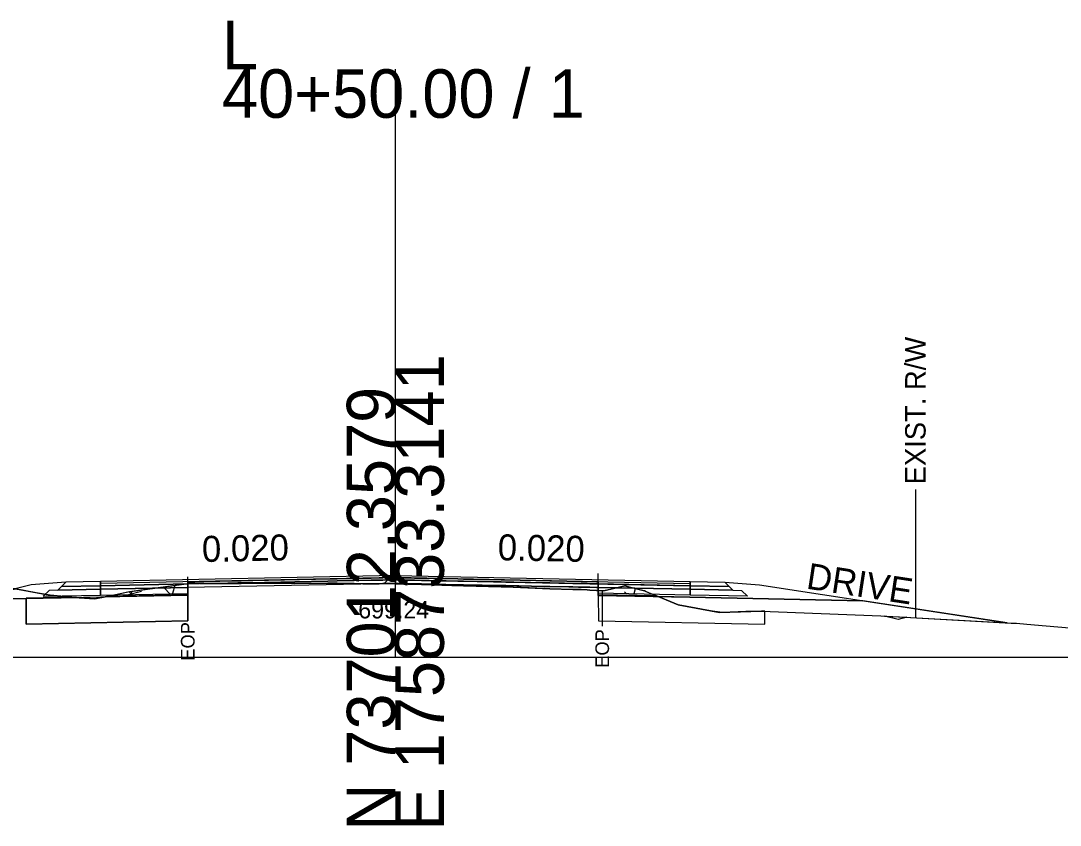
# Model space of a CAD drawing. Extents: x -26 to 4303, y -10 to 9577.
# Drawn here: x 3128.4 to 3188.4, y 490.3 to 536.7 of the extents above; entities that cross this region are included whole.
import ezdxf

# ---------------------------------------------------------------- set-up
doc = ezdxf.new("R2010")
doc.units = 0
for name, color, linetype in [('Exist CMT Pavement', 7, 'Continuous'), ('Old_Level_2', 7, 'Continuous'), ('Pattern 3', 7, 'Continuous'), ('Prop CMT Conc Surface', 7, 'Continuous'), ('Prop CMT Concrete Structures', 7, 'Continuous'), ('Prop CMT Pvmt Course 1', 7, 'Continuous'), ('Prop CMT Pvmt Course 1 CG', 7, 'Continuous'), ('Prop CMT Pvmt Course 1 Wedge', 7, 'Continuous'), ('Prop CMT Pvmt Course 2', 7, 'Continuous'), ('Prop CMT Pvmt Course 2 Wedge', 7, 'Continuous'), ('Prop CMT Pvmt Course 3', 7, 'Continuous'), ('Prop CMT Pvmt Surface', 7, 'Continuous'), ('Prop CMT Pvmt Surface Shoulder', 7, 'Continuous'), ('Prop CMT Pvmt Wedge Surface 1', 7, 'Continuous'), ('Prop CMT Pvmt Wedge Surface 2', 7, 'Continuous'), ('Prop CMT Pvmt Wedge Surface 3', 7, 'Continuous'), ('Prop CMT Shld Paved Course 1', 7, 'Continuous'), ('Prop CMT Shld Paved Course 2', 7, 'Continuous'), ('Prop CMT Shld Paved Course 3', 7, 'Continuous'), ('Prop CMT Slope Grass', 7, 'Continuous'), ('Prop CMT Subgrade Earthwork', 7, 'Continuous'), ('Prop Road Sect_ Recs - UC Shallow (Outline)', 7, 'Continuous'), ('Prop Shade Light', 7, 'Continuous'), ('Prop XS DDE Elevations', 7, 'Continuous'), ('Prop XS Ditch Standard Text', 7, 'Continuous'), ('Prop XS SE Text', 7, 'Continuous'), ('Prop XS Side Slope Text', 7, 'Continuous'), ('Prop XS Wedging', 7, 'Continuous'), ('Scratch_Level_2', 7, 'Continuous')]:
    doc.layers.add(name, color=color, linetype=linetype)

msp = doc.modelspace()

# ---------------------------------------------------------------- linework, layer by layer
at = {"layer": 'Exist CMT Pavement'}
for points in [[(3150, 504.72), (3133, 504.38)], [(3150, 504.72), (3167, 504.38)]]:
    msp.add_lwpolyline(points, dxfattribs=at)
at = {"layer": 'Old_Level_2'}
for p, q in [((3150, 500), (3150, 533.933)), ((3150, 500), (3150, 533.933)), ((3000, 500), (3150, 500)), ((3000, 500), (3150, 500)), ((3150, 500), (3300, 500)), ((3150, 500), (3300, 500))]:
    msp.add_line(p, q, dxfattribs=at)
at = {"layer": 'Pattern 3'}
for points in [[(3125.717, 503.359), (3128.694, 503.419), (3131.347, 503.472), (3130.695, 503.526), (3130.079, 503.576), (3129.976, 503.596), (3129.282, 503.728), (3128.095, 503.953)], [(3161.701, 503.854), (3161.702, 503.611), (3165.064, 503.544), (3164.47, 503.784), (3164.364, 503.827), (3163.928, 503.939), (3163.244, 504.114), (3162.704, 503.99), (3162.019, 503.841), (3161.702, 503.854)]]:
    msp.add_lwpolyline(points, dxfattribs=at)
for points in [[(3133.34, 503.512), (3134.569, 503.781), (3135.178, 503.865), (3137.579, 504.192), (3138.026, 504.253), (3138.024, 503.605)], [(3179.499, 502.305), (3179, 502.18), (3178.218, 502.375)]]:
    msp.add_lwpolyline(points, close=True, dxfattribs=at)
at = {"layer": 'Prop CMT Conc Surface'}
for points in [[(3138.024, 504.23), (3133, 504.13)], [(3133, 504.13), (3133, 503.921)], [(3133, 503.921), (3138.024, 504.022)], [(3138.024, 504.022), (3138.024, 504.23)], [(3161.702, 504.027), (3161.702, 504.236)], [(3161.702, 504.236), (3167, 504.13)], [(3167, 503.921), (3161.702, 504.027)], [(3167, 504.13), (3167, 503.921)]]:
    msp.add_lwpolyline(points, dxfattribs=at)
at = {"layer": 'Prop CMT Concrete Structures'}
for points in [[(3133, 504.13), (3133, 504.38)], [(3150, 504.595), (3138.024, 504.355)], [(3138.024, 504.355), (3138.024, 504.23)], [(3150, 504.595), (3161.702, 504.361)], [(3161.702, 504.361), (3161.702, 504.236)], [(3167, 504.13), (3167, 504.38)], [(3138.024, 504.23), (3133, 504.13)], [(3161.702, 504.236), (3167, 504.13)]]:
    msp.add_lwpolyline(points, dxfattribs=at)
at = {"layer": 'Prop CMT Pvmt Course 1'}
for points in [[(3138.024, 504.022), (3133, 503.921)], [(3133, 503.921), (3133, 503.588)], [(3133, 503.588), (3138.024, 503.689)], [(3138.024, 503.689), (3138.024, 504.022)], [(3161.702, 504.027), (3167, 503.921)], [(3161.702, 503.694), (3161.702, 504.027)], [(3167, 503.588), (3161.702, 503.694)], [(3167, 503.921), (3167, 503.588)]]:
    msp.add_lwpolyline(points, dxfattribs=at)
at = {"layer": 'Prop CMT Pvmt Course 1 Wedge'}
for points in [[(3149.063, 504.243), (3149.027, 504.242), (3148.977, 504.241)], [(3148.977, 504.241), (3149.027, 504.242)], [(3149.027, 504.242), (3149.063, 504.243)], [(3149.356, 504.249), (3150, 504.261)], [(3150, 504.241), (3149.356, 504.249)], [(3150, 504.261), (3150, 504.241)], [(3150, 504.261), (3150.044, 504.261), (3150.372, 504.254), (3150.498, 504.252), (3150.722, 504.247), (3151.108, 504.239), (3151.502, 504.231), (3153.609, 504.189), (3153.934, 504.183), (3156.11, 504.139), (3156.366, 504.134), (3158.611, 504.089), (3158.904, 504.083), (3160.235, 504.057), (3160.563, 504.05), (3160.711, 504.047), (3161.071, 504.04), (3161.214, 504.037), (3161.596, 504.03), (3161.702, 504.027)], [(3161.702, 503.854), (3161.596, 503.858), (3161.214, 503.874), (3161.071, 503.893), (3160.711, 503.902), (3160.563, 503.907), (3160.235, 503.914), (3158.904, 503.952), (3158.611, 503.961), (3156.366, 504.063), (3156.11, 504.074), (3153.934, 504.129), (3153.609, 504.137), (3151.502, 504.199), (3151.108, 504.213), (3150.722, 504.226), (3150.498, 504.233), (3150.372, 504.233), (3150.044, 504.24), (3150, 504.241)], [(3161.702, 504.027), (3161.702, 503.854)]]:
    msp.add_lwpolyline(points, dxfattribs=at)
at = {"layer": 'Prop CMT Pvmt Course 2'}
for points in [[(3133, 504.38), (3131, 504.34), (3130.745, 504.085)], [(3133, 504.13), (3133, 504.38)], [(3167, 504.38), (3169, 504.34), (3169.255, 504.085)], [(3167, 504.13), (3167, 504.38)], [(3130.745, 504.085), (3133, 504.13)], [(3169.255, 504.085), (3167, 504.13)]]:
    msp.add_lwpolyline(points, dxfattribs=at)
at = {"layer": 'Prop CMT Pvmt Course 2 Wedge'}
for points in [[(3131, 504.34), (3129, 504.18), (3121, 502.18), (3099.691, 507.507)], [(3169, 504.34), (3171, 504.18), (3185.298, 501.984)]]:
    msp.add_lwpolyline(points, dxfattribs=at)
at = {"layer": 'Prop CMT Pvmt Course 3'}
for points in [[(3133, 504.13), (3130.745, 504.085), (3130.532, 503.872)], [(3130.532, 503.872), (3133, 503.921)], [(3133, 503.921), (3133, 504.13)], [(3167, 504.13), (3169.255, 504.085), (3169.468, 503.872)], [(3167, 503.921), (3167, 504.13)], [(3169.468, 503.872), (3167, 503.921)]]:
    msp.add_lwpolyline(points, dxfattribs=at)
at = {"layer": 'Prop CMT Pvmt Surface'}
for points in [[(3150, 504.47), (3133, 504.13)], [(3133, 504.13), (3133, 504.38)], [(3150, 504.47), (3167, 504.13)], [(3167, 504.13), (3167, 504.38)]]:
    msp.add_lwpolyline(points, dxfattribs=at)
at = {"layer": 'Prop CMT Pvmt Surface Shoulder'}
for points in [[(3138.026, 504.253), (3138.221, 504.28), (3138.426, 504.281), (3138.705, 504.263), (3140.906, 504.267), (3141.104, 504.266), (3141.774, 504.27), (3143.605, 504.267), (3144.206, 504.264), (3146.106, 504.276), (3146.638, 504.271), (3148.607, 504.237), (3149.027, 504.242), (3149.28, 504.25), (3149.998, 504.241)], [(3149.998, 504.241), (3150.044, 504.24), (3150.372, 504.233), (3150.498, 504.233), (3150.722, 504.226), (3151.108, 504.213), (3151.502, 504.199), (3153.609, 504.137), (3153.934, 504.129), (3156.11, 504.074), (3156.366, 504.063), (3158.611, 503.961), (3158.904, 503.952), (3160.235, 503.914), (3160.563, 503.907), (3160.711, 503.902), (3161.071, 503.893), (3161.214, 503.874), (3161.596, 503.858), (3161.701, 503.854)]]:
    msp.add_lwpolyline(points, dxfattribs=at)
at = {"layer": 'Prop CMT Pvmt Wedge Surface 1'}
for p, q in [((3133.018, 503.463), (3125.535, 503.314)), ((3138.024, 503.563), (3133.018, 503.463)), ((3161.703, 503.569), (3166.982, 503.463)), ((3166.982, 503.463), (3176.968, 503.263))]:
    msp.add_line(p, q, dxfattribs=at)
for points in [[(3138.024, 503.563), (3138.026, 504.253)], [(3161.703, 503.569), (3161.701, 503.854)]]:
    msp.add_lwpolyline(points, dxfattribs=at)
at = {"layer": 'Prop CMT Pvmt Wedge Surface 2'}
for points in [[(3138.024, 504.355), (3138.221, 504.359), (3138.426, 504.363), (3138.705, 504.369), (3140.906, 504.413), (3141.104, 504.417), (3141.774, 504.43), (3143.605, 504.467), (3144.206, 504.479), (3146.106, 504.517), (3146.638, 504.528), (3148.607, 504.567), (3149.027, 504.575), (3149.28, 504.58), (3150, 504.595)], [(3150, 504.47), (3149.28, 504.455), (3149.027, 504.45), (3148.607, 504.442), (3146.638, 504.403), (3146.106, 504.392), (3144.206, 504.354), (3143.605, 504.342), (3141.774, 504.305), (3141.104, 504.292), (3140.906, 504.288), (3139.76, 504.265), (3138.705, 504.263), (3138.426, 504.281), (3138.221, 504.28), (3138.024, 504.253)], [(3138.024, 504.253), (3138.024, 504.355)], [(3150, 504.595), (3150, 504.47)], [(3150, 504.595), (3150.044, 504.594), (3150.372, 504.587), (3150.498, 504.585), (3150.722, 504.58), (3151.108, 504.573), (3151.502, 504.565), (3153.609, 504.523), (3153.934, 504.516), (3156.11, 504.473), (3156.366, 504.467), (3158.611, 504.423), (3158.904, 504.417), (3160.235, 504.39), (3160.563, 504.384), (3160.711, 504.381), (3161.071, 504.373), (3161.214, 504.371), (3161.596, 504.363), (3161.702, 504.361)], [(3161.702, 504.236), (3161.596, 504.238), (3161.214, 504.246), (3161.071, 504.248), (3160.711, 504.256), (3160.563, 504.259), (3160.235, 504.265), (3158.904, 504.292), (3158.611, 504.298), (3156.366, 504.342), (3156.11, 504.348), (3153.934, 504.391), (3153.609, 504.398), (3151.502, 504.44), (3151.108, 504.448), (3150.722, 504.455), (3150.498, 504.46), (3150.372, 504.462), (3150.044, 504.469), (3150, 504.47)], [(3161.702, 504.361), (3161.702, 504.236)]]:
    msp.add_lwpolyline(points, dxfattribs=at)
at = {"layer": 'Prop CMT Pvmt Wedge Surface 3'}
for points in [[(3139.762, 504.265), (3140.906, 504.288)], [(3150, 504.261), (3149.356, 504.249), (3149.28, 504.25), (3149.063, 504.243), (3149.027, 504.242), (3148.977, 504.241), (3148.607, 504.237), (3146.638, 504.271), (3146.106, 504.276), (3144.206, 504.264), (3143.605, 504.267), (3141.774, 504.27), (3141.104, 504.266), (3140.906, 504.267), (3139.762, 504.265)], [(3140.906, 504.288), (3141.104, 504.292), (3141.774, 504.305), (3143.605, 504.342), (3144.206, 504.354), (3146.106, 504.392), (3146.638, 504.403), (3148.607, 504.442), (3149.027, 504.45), (3149.28, 504.455), (3150, 504.47)], [(3150, 504.47), (3150, 504.261)], [(3150, 504.47), (3150.044, 504.469), (3150.372, 504.462), (3150.498, 504.46), (3150.722, 504.455), (3151.108, 504.448), (3151.502, 504.44), (3153.609, 504.398), (3153.934, 504.391), (3156.11, 504.348), (3156.366, 504.342), (3158.611, 504.298), (3158.904, 504.292), (3160.235, 504.265), (3160.563, 504.259), (3160.711, 504.256), (3161.071, 504.248), (3161.214, 504.245), (3161.596, 504.238), (3161.702, 504.236)], [(3161.702, 504.027), (3161.596, 504.03), (3161.214, 504.037), (3161.071, 504.04), (3160.711, 504.047), (3160.563, 504.05), (3160.235, 504.057), (3158.904, 504.083), (3158.611, 504.089), (3156.366, 504.134), (3156.11, 504.139), (3153.934, 504.183), (3153.609, 504.189), (3151.502, 504.231), (3151.108, 504.239), (3150.722, 504.247), (3150.498, 504.252), (3150.372, 504.254), (3150.044, 504.261), (3150, 504.261)], [(3161.702, 504.236), (3161.702, 504.027)]]:
    msp.add_lwpolyline(points, dxfattribs=at)
at = {"layer": 'Prop CMT Shld Paved Course 1'}
for points in [[(3133, 503.921), (3133, 504.38)], [(3167, 503.921), (3167, 504.38)], [(3150, 504.261), (3133, 503.921)], [(3150, 504.261), (3167, 503.921)]]:
    msp.add_lwpolyline(points, dxfattribs=at)
at = {"layer": 'Prop CMT Shld Paved Course 2'}
for points in [[(3133, 504.38), (3131, 504.34)], [(3167, 504.38), (3169, 504.34)]]:
    msp.add_lwpolyline(points, dxfattribs=at)
at = {"layer": 'Prop CMT Shld Paved Course 3'}
for points in [[(3150, 504.72), (3133, 504.38)], [(3133, 504.38), (3133, 504.13)], [(3138.024, 504.355), (3150, 504.595)], [(3138.024, 504.23), (3138.024, 504.355)], [(3150, 504.47), (3150, 504.72)], [(3150, 504.72), (3167, 504.38)], [(3150, 504.595), (3150, 504.47), (3150, 504.47)], [(3161.702, 504.361), (3150, 504.595)], [(3161.702, 504.236), (3161.702, 504.361)], [(3167, 504.38), (3167, 504.13)], [(3133, 504.13), (3138.024, 504.23)], [(3167, 504.13), (3161.702, 504.236)]]:
    msp.add_lwpolyline(points, dxfattribs=at)
at = {"layer": 'Prop CMT Slope Grass'}
msp.add_lwpolyline([(3125.579, 504.431), (3130.075, 503.576), (3132.661, 503.363), (3134.592, 503.785), (3138.221, 504.28), (3138.705, 504.263), (3141.104, 504.266), (3141.774, 504.27), (3143.605, 504.267), (3144.206, 504.264), (3146.106, 504.276), (3148.118, 504.241), (3148.607, 504.237), (3149.28, 504.25), (3150.044, 504.24), (3150.722, 504.226), (3151.108, 504.213), (3153.266, 504.149), (3153.609, 504.137), (3156.366, 504.063), (3158.904, 503.952), (3160.235, 503.914), (3160.711, 503.902), (3161.071, 503.893), (3161.596, 503.858), (3162.019, 503.841), (3162.743, 503.999), (3163.244, 504.114), (3164.364, 503.827), (3166.315, 503.032), (3168.704, 502.579), (3171.121, 502.665), (3178.001, 502.387), (3185.528, 501.972), (3185.841, 501.959), (3186.429, 501.906), (3192.233, 501.417)], dxfattribs=at)
at = {"layer": 'Prop CMT Subgrade Earthwork'}
for points in [[(3133, 503.921), (3130.532, 503.872), (3130.032, 503.862), (3129.692, 503.522)], [(3133, 503.588), (3133, 503.921)], [(3167, 503.921), (3169.468, 503.872), (3169.968, 503.862), (3170.308, 503.522)], [(3167, 503.588), (3167, 503.921)], [(3129.692, 503.522), (3133, 503.588)], [(3170.308, 503.522), (3167, 503.588)]]:
    msp.add_lwpolyline(points, dxfattribs=at)
at = {"layer": 'Prop Road Sect_ Recs - UC Shallow (Outline)'}
for points in [[(3138.024, 502.105), (3128.694, 501.919), (3128.694, 503.419), (3131.347, 503.472), (3131.802, 503.434), (3132.661, 503.363), (3133.353, 503.514), (3138.024, 503.605)], [(3161.717, 502.111), (3171.314, 501.919), (3171.319, 502.657), (3170.217, 502.633), (3168.876, 502.585), (3168.15, 502.684), (3166.307, 503.035), (3165.064, 503.544), (3161.703, 503.611)]]:
    msp.add_lwpolyline(points, close=True, dxfattribs=at)
at = {"layer": 'Prop Shade Light'}
for p, q in [((3129.675, 503.438), (3128.694, 503.419)), ((3128.694, 503.419), (3128.694, 501.919)), ((3131.34, 503.472), (3129.675, 503.438)), ((3138.024, 503.605), (3133.353, 503.514)), ((3138.024, 502.105), (3138.024, 503.605)), ((3161.703, 503.611), (3161.717, 502.111)), ((3168.704, 502.579), (3166.315, 503.032)), ((3171.121, 502.665), (3168.704, 502.579)), ((3171.319, 502.657), (3171.121, 502.665)), ((3171.314, 501.919), (3171.319, 502.657)), ((3128.694, 501.919), (3138.024, 502.105)), ((3161.717, 502.111), (3171.314, 501.919))]:
    msp.add_line(p, q, dxfattribs=at)
for points in [[(3133.353, 503.514), (3132.661, 503.363), (3131.34, 503.472)], [(3166.315, 503.032), (3165.064, 503.544), (3161.703, 503.611)]]:
    msp.add_lwpolyline(points, dxfattribs=at)
at = {"layer": 'Prop XS DDE Elevations'}
for points in [[(3138.426, 504.281), (3138.705, 504.263), (3138.221, 504.28)], [(3146.106, 504.276), (3146.638, 504.271), (3148.607, 504.237), (3148.118, 504.241)], [(3130.075, 503.576), (3131.753, 503.438), (3125.535, 503.314), (3128.093, 503.953)], [(3138.024, 503.563), (3133.13, 503.465), (3134.592, 503.785), (3138.026, 504.253)], [(3138.705, 504.263), (3141.104, 504.266), (3140.906, 504.267)], [(3148.607, 504.237), (3149.027, 504.242), (3149.28, 504.25)], [(3150.372, 504.233), (3150.498, 504.233), (3150.722, 504.226), (3150.044, 504.24)], [(3153.609, 504.137), (3156.366, 504.063), (3156.11, 504.074), (3153.934, 504.129)], [(3156.366, 504.063), (3158.904, 503.952), (3158.611, 503.961)], [(3160.235, 503.914), (3160.563, 503.907), (3160.711, 503.902)], [(3161.071, 503.893), (3161.596, 503.858), (3161.214, 503.874)], [(3161.703, 503.569), (3161.701, 503.854), (3162.019, 503.841), (3162.743, 503.999), (3163.244, 504.114), (3164.364, 503.827), (3165.168, 503.499)], [(3133.13, 503.465), (3133.018, 503.463), (3131.753, 503.438), (3132.661, 503.363)], [(3166.315, 503.032), (3168.704, 502.579), (3171.121, 502.665), (3178.001, 502.387), (3185.298, 501.984), (3176.968, 503.263), (3166.982, 503.463), (3165.168, 503.499)]]:
    msp.add_lwpolyline(points, close=True, dxfattribs=at)
at = {"layer": 'Prop XS Ditch Standard Text'}
for p, q in [((3180, 509.678), (3180, 502.277)), ((3138.024, 504.253), (3138.024, 502.203)), ((3161.934, 503.845), (3161.934, 501.794))]:
    msp.add_line(p, q, dxfattribs=at)
at = {"layer": 'Prop XS Wedging'}
for p, q in [((3138.024, 504.253), (3138.024, 504.649)), ((3138.025, 504.355), (3138.026, 504.253)), ((3138.026, 504.253), (3138.221, 504.28)), ((3149.562, 504.461), (3149.358, 504.249)), ((3149.358, 504.249), (3149.562, 504.461)), ((3149.562, 504.461), (3149.358, 504.249)), ((3149.562, 504.461), (3149.995, 504.47)), ((3149.995, 504.47), (3150, 504.47)), ((3150, 504.47), (3150.005, 504.47)), ((3150.005, 504.47), (3161.701, 504.236)), ((3161.701, 503.854), (3161.701, 504.831)), ((3161.701, 504.236), (3161.701, 504.361)), ((3149.358, 504.249), (3149.998, 504.241)), ((3149.998, 504.241), (3150.044, 504.24)), ((3156.366, 504.063), (3158.904, 503.952)), ((3161.701, 503.854), (3161.701, 504.236))]:
    msp.add_line(p, q, dxfattribs=at)
for points in [[(3150.002, 504.595), (3133.002, 504.255)], [(3150, 504.595), (3149.998, 504.595), (3138.025, 504.355)], [(3138.221, 504.28), (3138.426, 504.281), (3138.705, 504.263), (3140.906, 504.267), (3141.104, 504.266), (3141.774, 504.27), (3143.605, 504.267), (3144.206, 504.264), (3146.106, 504.276), (3146.638, 504.271), (3148.607, 504.237)], [(3150.005, 504.47), (3149.562, 504.461)], [(3150, 504.47), (3149.995, 504.47), (3149.562, 504.461)], [(3149.995, 504.47), (3166.995, 504.13)], [(3149.995, 504.47), (3149.995, 504.47)], [(3149.998, 504.595), (3166.998, 504.255)], [(3161.701, 504.361), (3150.002, 504.595), (3150, 504.595)], [(3161.701, 504.236), (3150.005, 504.47), (3150, 504.47)], [(3150.005, 504.47), (3150.005, 504.47)], [(3148.607, 504.237), (3149.28, 504.25), (3149.358, 504.249)], [(3150.044, 504.24), (3150.372, 504.233), (3150.498, 504.233), (3150.722, 504.226)], [(3150.722, 504.226), (3151.108, 504.213), (3151.502, 504.201), (3153.266, 504.149), (3153.609, 504.137)], [(3153.609, 504.137), (3153.934, 504.129), (3156.11, 504.074), (3156.366, 504.063)], [(3158.904, 503.952), (3160.235, 503.914), (3160.563, 503.907), (3160.711, 503.902), (3161.071, 503.893)], [(3161.071, 503.893), (3161.596, 503.858), (3161.701, 503.854)]]:
    msp.add_lwpolyline(points, dxfattribs=at)
at = {"layer": 'Scratch_Level_2'}
for p, q in [((3134.613, 503.62), (3135.364, 503.822)), ((3134.63, 503.79), (3134.796, 503.624)), ((3134.801, 503.813), (3134.75, 503.623)), ((3136.675, 503.983), (3136.99, 503.668)), ((3137.278, 504.145), (3137.151, 503.671)), ((3163.224, 503.779), (3163.341, 503.661)), ((3163.828, 503.941), (3163.751, 503.653))]:
    msp.add_line(p, q, dxfattribs=at)

# ---------------------------------------------------------------- texts
at = {"layer": 'Old_Level_2'}
for s, p in [('L', (3140, 533.933)), ('L', (3140, 533.933)), ('40+50.00 / 1', (3140, 531.133)), ('40+50.00 / 1', (3140, 531.133))]:
    msp.add_text(s, height=2.8, dxfattribs=at).set_placement(p)
for s, p in [('E 1758733.3141', (3152.8, 490)), ('E 1758733.3141', (3152.8, 490)), ('N 737012.3579', (3150, 490)), ('N 737012.3579', (3150, 490))]:
    msp.add_text(s, height=2.8, rotation=90, dxfattribs=at).set_placement(p)
at = {"layer": 'Prop CMT Pvmt Course 1 CG'}
msp.add_text('699.24', height=1, dxfattribs=at).set_placement((3147.861, 502.241))
at = {"layer": 'Prop XS Ditch Standard Text'}
for s, height, p in [('EXIST. R/W', 1.1811, (3180.591, 509.981)), ('EOP', 0.7874, (3138.418, 499.804)), ('EOP', 0.7874, (3162.327, 499.396))]:
    msp.add_text(s, height=height, rotation=90, dxfattribs=at).set_placement(p)
at = {"layer": 'Prop XS SE Text'}
for rotation, p in [(1.14576, (3138.856, 505.497)), (358.85424, (3155.896, 505.602))]:
    msp.add_text('0.020', height=1.5, rotation=rotation, dxfattribs=at).set_placement(p)
at = {"layer": 'Prop XS Side Slope Text'}
msp.add_text('DRIVE', height=1.5, rotation=351.27072, dxfattribs=at).set_placement((3173.656, 503.969))

doc.saveas('drawing.dxf')
